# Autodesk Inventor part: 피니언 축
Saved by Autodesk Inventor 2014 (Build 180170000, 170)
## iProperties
Created: 2025-06
Part Number: 피니언 축
Material: 일반
Document SubType Name: Modeling
Designer: dg
Density: 1 g/cm^3
Appearance: 기본값
Author: dg
Author: jhkim
Creation Date: 2025-05-27
Sending System: Autodesk Inventor 2026
Preprocessor: ST-DEVELOPER v20.1
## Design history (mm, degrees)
node "피니언 축1"
node "솔리드1"
node "기준1"
